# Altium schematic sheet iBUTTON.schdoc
size 221 x 209 mm; Symbol: Drawing-Symbol_A4; @Project Name: Hưhwwuey; @Page Count: 7; @Update Date: 2026-10-18; @Create Date: 2026-10-18; @Schematic Name: Schematic1; @Page No: 7; @Page Name: P1; Company: EasyEDA.com; Version: V1.0; Page Size: A4; Device: Drawing-Symbol_A4; @Create Time: 12:26:59; @Update Time: 12:26:59; Border: 1; Width: 869.9999999999999; Height: 825; Region Start: 1; X Region Count: 6; Y Region Count: 4; Blade Width: 10; Title Block Position: 3; @Board Name: Board1
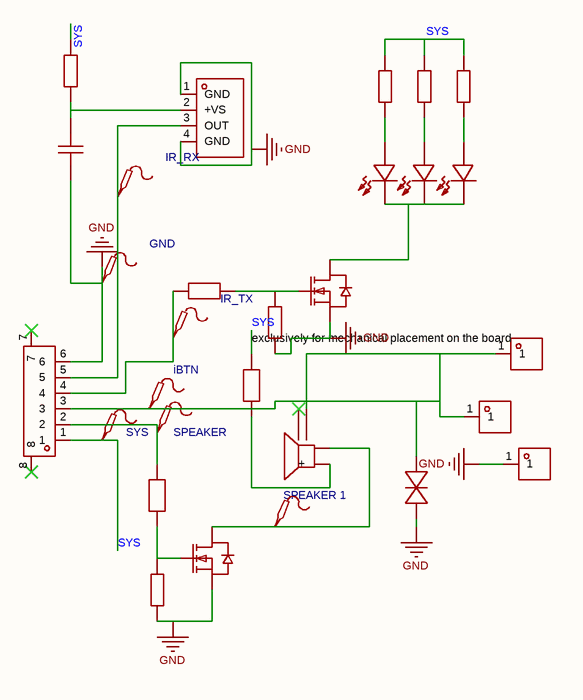
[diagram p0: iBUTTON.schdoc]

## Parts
BUZZER1  2.7kHz  [BUZ-SMD_4P-L8.5-W8.5-P8.50-BR]  (value not drawn)
C90  100nF  [C0402]  (value not drawn)
CN1  YTC1P-3515-M20  [CONN-SMD_YTC1P-3515-M20]  (value not drawn)
CN2  YTC1P-3515-M20  [CONN-SMD_YTC1P-3515-M20]  (value not drawn)
CN3  YTC1P-3515-M20  [CONN-SMD_YTC1P-3515-M20]  (value not drawn)
FPC2  5051100697  [FPC-SMD_6P-P0.50_5051100697]  (value not drawn)
Q5  DMN2058UW-7  [SOT-323-3_L2.2-W1.3-P1.30-LS2.1-BR]  (value not drawn)
Q6  DMN2058UW-7  [SOT-323-3_L2.2-W1.3-P1.30-LS2.1-BR]  (value not drawn)
R76  10Ω  [R0402]  (value not drawn)
R77  150Ω  [R0402]  (value not drawn)
R78  10K  [R0402]  (value not drawn)
R79  22Ω  [R0603]  (value not drawn)
R80  150Ω  [R0402]  (value not drawn)
R81  10K  [R0402]  (value not drawn)
R82  39Ω  [R0402]  (value not drawn)
R83  39Ω  [R0402]  (value not drawn)
R84  39Ω  [R0402]  (value not drawn)
TP19  SYS  [Test-Point-0.5mm]
TP20  SPEAKER  [Test-Point-0.5mm]
TP21  SPEAKER 1  [Test-Point-0.5mm]
TP22  iBTN  [Test-Point-0.5mm]
TP23  IR_TX  [Test-Point-0.5mm]
TP24  IR_RX  [Test-Point-0.5mm]
TP25  GND  [Test-Point-0.5mm]
U44  ESD230B1W0201E6327XTSA1  [WLL-2-1_L0.6-W0.3-BI]  (value not drawn)
U45  VSMY14940  [LED-SMD_VSMY14940]  (value not drawn)
U46  VSMY14940  [LED-SMD_VSMY14940]  (value not drawn)
U47  VSMY14940  [LED-SMD_VSMY14940]  (value not drawn)
U48  TSOP75338TR  [SENSOR-SMD_TSOP75238TR]  (value not drawn)

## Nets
GND: C90.2 CN3.1 FPC2.6 Q5.2(S) Q6.2(S) R78.1 R81.1 TP25.1 U44.1(C) U48.1(GND) U48.4(GND)
SYS: FPC2.1 R76.1 R79.2 R82.2 R83.2 R84.2 TP19.1
NetBUZZER1_1: BUZZER1.1(+) R79.1
NetBUZZER1_2: BUZZER1.2 Q5.3(D) TP21.1
NetBUZZER1_3: BUZZER1.3 CN1.1 CN2.1 FPC2.3 TP22.1 U44.2(A)
NetC90_1: C90.1 R76.2 U48.2(+VS)
NetFPC2_2: FPC2.2 R77.2 TP20.1
NetFPC2_4: FPC2.4 R80.2 TP23.1
NetFPC2_5: FPC2.5 TP24.1 U48.3(OUT)
NetQ5_1: Q5.1(G) R77.1 R78.2
NetQ6_1: Q6.1(G) R80.1 R81.2
NetQ6_3: Q6.3(D) U45.1(C) U46.1(C) U47.1(C)
NetR82_1: R82.1 U45.2(A)
NetR83_1: R83.1 U46.2(A)
NetR84_1: R84.1 U47.2(A)

Not connected (* = marked no-connect by the designer): BUZZER1 4*; FPC2 7* 8*

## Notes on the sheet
- (near R81) exclusively for mechanical placement on the board

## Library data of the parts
BUZZER1 = MLT-8530: Driver Circuitry:Passive (Externally Driven) Technology:Electromagnetic Voltage Rating:3.6V Voltage - Supply:2.5V~4.5V Voltage - Supply:2.5V~4.5V Frequency:2.7kHz Current Consumption:95mA Sound Pressure Level(SPL):80dB Diameter(φD):- Length:8.5mm Width:8.; Manufacturer: 华能; AddInBom: yes; ModelId: 1f0184a0c0d240599d1bdf7286819a4f0819f05c4eef4c71ace90d822a990e87; ModelName: BUZ-SMD_4P-L8.5-W8.5-H3.0; ModelTransform: 342.519,342.519,0,0,0,0,0,0,0; Voltage Rating: 3.6V; Current Consumption: 95mA; Sound Pressure Level(SPL): 80dB
C90 = CAP_0402: Symbol: CAP_OLD; 3D Model: b7d13df3e9464d7a99d0651d1a5b4d570819f05c4eef4c71ace90d822a990e87; 3D Model Transform: 39.37,19.685,0,0,0,0,0,0,0; ConvertToPcb: yes; ModelName: C0402_L1.0-W0.5-H0.5
CN1-CN3 = YTC1P-3515-M20: Type:Pogo Pin Number of Pins:1P Overall Length/Height:4mm Contact Material:Brass Contact Plating:Gold; Manufacturer: YIYUAN(怡远); AddInBom: yes; ModelId: e956e29c821d4094900f1c4d8f713bf40819f05c4eef4c71ace90d822a990e87; ModelTransform: 78.624,78.682,0,0,0,0,0,0,0; Overall Length/Height: 4mm
FPC2 = 5051100697: Locking Feature:Hinged Lid Contact Type:Bottom Contact Number of Contacts:6P Pitch:0.5mm Mounting Type:Surface Mount, Right Angle FFC, FCB Thickness:0.3mm FFC, FCB Thickness:0.3mm Height Above Board:1.9mm Contact Material:Copper alloy Contact Plating:Gold; Manufacturer: MOLEX; AddInBom: yes; ModelId: d0ab96b3bf8e4699890f8890e4413f070819f05c4eef4c71ace90d822a990e87; ModelTransform: 334.645,208.661,0,0,0,0,0,-43.583,0; Number of Contacts: 6P; Pitch: 0.5mm; FFC, FCB Thickness: 0.3mm
Q5 Q6 = DMN2058UW-7: Number:1 N-channel Drain to Source Voltage:20V Current - Continuous Drain(Id):3.5A RDS(on):31.5mΩ@10V Pd - Power Dissipation:0.7mW Gate Threshold Voltage (Vgs(th)):1.2V Gate Charge(Qg):7.7nC@10V Input Capacitance(Ciss):281pF Reverse Transfer Capacitance (; Manufacturer: DIODES(美台); AddInBom: yes; ModelId: 00b47c5ba4b548a981fce2870442aba00819f05c4eef4c71ace90d822a990e87; ModelName: SOT-323-3_L2.0-W1.3-H1.0-LS2.1-P1.30; ModelTransform: 78.74,82.677,0,90,0,0,-0.001,-0.001,0; Drain to Source Voltage: 20V; Current - Continuous Drain(Id): 3.5A; Pd - Power Dissipation: 0.7mW; Gate Threshold Voltage (Vgs(th)): 1.2V; Input Capacitance(Ciss): 281pF; Reverse Transfer Capacitance (Crss@Vds): 39pF; Output Capacitance(Coss): 50pF
R76 = RC-02W100JT: Type:Thick Film Resistors Resistance:10Ω Tolerance:±5% Tolerance:±5% Power(Watts):62.5mW Voltage-Supply(Max):50V Temperature Coefficient:±200ppm/℃ Temperature Coefficient:±200ppm/℃ Operating Temperature:-55℃~+155℃ Operating Temperature:-55℃~+155℃; Manufacturer: FH(风华); AddInBom: yes; ModelId: efdecb7dae4442949d28eecaf748420f0819f05c4eef4c71ace90d822a990e87; ModelName: R0402_L1.0-W0.5-H0.4; ModelTransform: 39.37,19.685,0,0,0,0,0,0,0; Tolerance: ±5%; Power(Watts): 62.5mW; Voltage-Supply(Max): 50V
R77 R80 = AT0402BRD07150RL: Type:Thin Film Resistor Resistance:150Ω Tolerance:±0.1% Tolerance:±0.1% Power(Watts):62.5mW Voltage-Supply(Max):50V Temperature Coefficient:±25ppm/℃ Temperature Coefficient:±25ppm/℃ Operating Temperature:-55℃~+155℃ Operating Temperature:-55℃~+155℃; Manufacturer: YAGEO(国巨); AddInBom: yes; ModelId: efdecb7dae4442949d28eecaf748420f0819f05c4eef4c71ace90d822a990e87; ModelName: R0402_L1.0-W0.5-H0.4; ModelTransform: 39.37,19.685,0,0,0,0,0,0,0; Tolerance: ±0.1%; Power(Watts): 62.5mW; Voltage-Supply(Max): 50V
R78 R81 = Res_0402: Symbol: Res; 3D Model: efdecb7dae4442949d28eecaf748420f0819f05c4eef4c71ace90d822a990e87; 3D Model Transform: 39.37,19.685,0,0,0,0,0,0,0; ConvertToPcb: yes; ModelName: R0402_L1.0-W0.5-H0.4
R79 = WR06X220JTL_C384264: Type:Thick Film Resistor Resistance:22Ω Tolerance:±5% Tolerance:±5% Power(Watts):100mW Voltage-Supply(Max):75V Temperature Coefficient:±100ppm/℃ Temperature Coefficient:±100ppm/℃ Operating Temperature:-55℃~+155℃ Operating Temperature:-55℃~+155℃; Manufacturer: Walsin(华新科); AddInBom: yes; ModelId: 112863783b5b41f1b5254f87eedc79320819f05c4eef4c71ace90d822a990e87; ModelTransform: 31.8897,63.7794,0,90,0,0,0,0,0; Tolerance: ±5%; Power(Watts): 100mW; Voltage-Supply(Max): 75V
R82-R84 = WR04X390JTR: Resistance: Tolerance:±5% Tolerance:±5% Power(Watts): Overload Voltage (Max): Temperature Coefficient:±100ppm/℃ Temperature Coefficient:±100ppm/℃ Operating Temperature Range:-55℃~+155℃ Operating Temperature Range:-55℃~+155℃; Manufacturer: Walsin(华新科); AddInBom: yes; ModelId: efdecb7dae4442949d28eecaf748420f0819f05c4eef4c71ace90d822a990e87; ModelName: R0402_L1.0-W0.5-H0.4; ModelTransform: 39.37,19.685,0,0,0,0,0,0,0; Tolerance: ±5%
TP19-TP25 = Test-Point: Test Point 测试点; AddInBom: yes
U44 = ESD230B1W0201E6327XTSA1: Reverse Stand-Off Voltage (Vrwm):5.5V Clamping Voltage:15V Peak Pulse Current (Ipp):3A@8/20us Peak Pulse Power Dissipation (Ppp):56W Voltage - Breakdown:6.05V Reverse Leakage Current (Ir):1nA Operating Temperature:-55℃~+125℃ Operating Temperature:-55℃~+12; Manufacturer: Infineon(英飞凌); AddInBom: yes; ModelId: e9ba6bad375e4bb7980be781c89bfdc60819f05c4eef4c71ace90d822a990e87; ModelTransform: 22.8346,11.0236,0,0,0,0,0,0,0; Reverse Stand-Off Voltage (Vrwm): 5.5V; Clamping Voltage: 15V; Peak Pulse Power Dissipation (Ppp): 56W; Voltage - Breakdown: 6.05V; Reverse Leakage Current (Ir): 1nA; level of protection: IEC 61000-4-4；IEC 61000-4-5；IEC 61000-4-2; Junction Capacitance: 7pF
U45-U47 = VSMY14940: Voltage - Forward(Vf):1.48V Voltage - Forward(Vf):1.48V Pd - Power Dissipation:119mW Wavelength:940nm Wavelength:940nm Radiant Intensity:15mW/sr；90mW/sr；560mW/sr Current - DC Forward(If):70mA Voltage - DC Reverse(Vr):5V Viewing Angle:9° Operating Temperat; Manufacturer: VISHAY(威世); AddInBom: yes; ModelId: 01bb82a8d6ff484f824ce80a93b554670819f05c4eef4c71ace90d822a990e87; ModelName: LED-SMD-L3.0-W2.5-H1.2_VSMY14940; ModelTransform: 118.11,99.606,0,0,0,0,-0.001,-27.996,0; Voltage - Forward(Vf): 1.48V; Pd - Power Dissipation: 119mW; Wavelength: 940nm; Current - DC Forward(If): 70mA; Voltage - DC Reverse(Vr): 5V; Viewing Angle: 9°; Half wave width: 55nm
U48 = TSOP75338TR: Voltage - Supply:2.5V~5.5V Voltage - Supply:2.5V~5.5V Current - Supply:350uA Transmission Distance:45m Frequency - Center:38kHz Operating Temperature:-25℃~+85℃ Operating Temperature:-25℃~+85℃; Manufacturer: VISHAY(威世); AddInBom: yes; ModelId: 8ced062818ce420786a30423c094f33e0819f05c4eef4c71ace90d822a990e87; ModelTransform: 267.716,125.984,0,0,0,0,0,35.433,0; Current - Supply: 350uA; Transmission Distance: 45m; Frequency - Center: 38kHz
